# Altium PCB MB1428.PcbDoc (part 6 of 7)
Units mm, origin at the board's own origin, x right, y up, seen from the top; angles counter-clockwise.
Board outline 55.88 x 152.4 mm, 4 copper layers (Top Layer, Signal Layer 1, Signal Layer 2, Bottom Layer), stack 1.614 mm thick; 396 components, 227 nets, 1346 pads, 1469 vias.
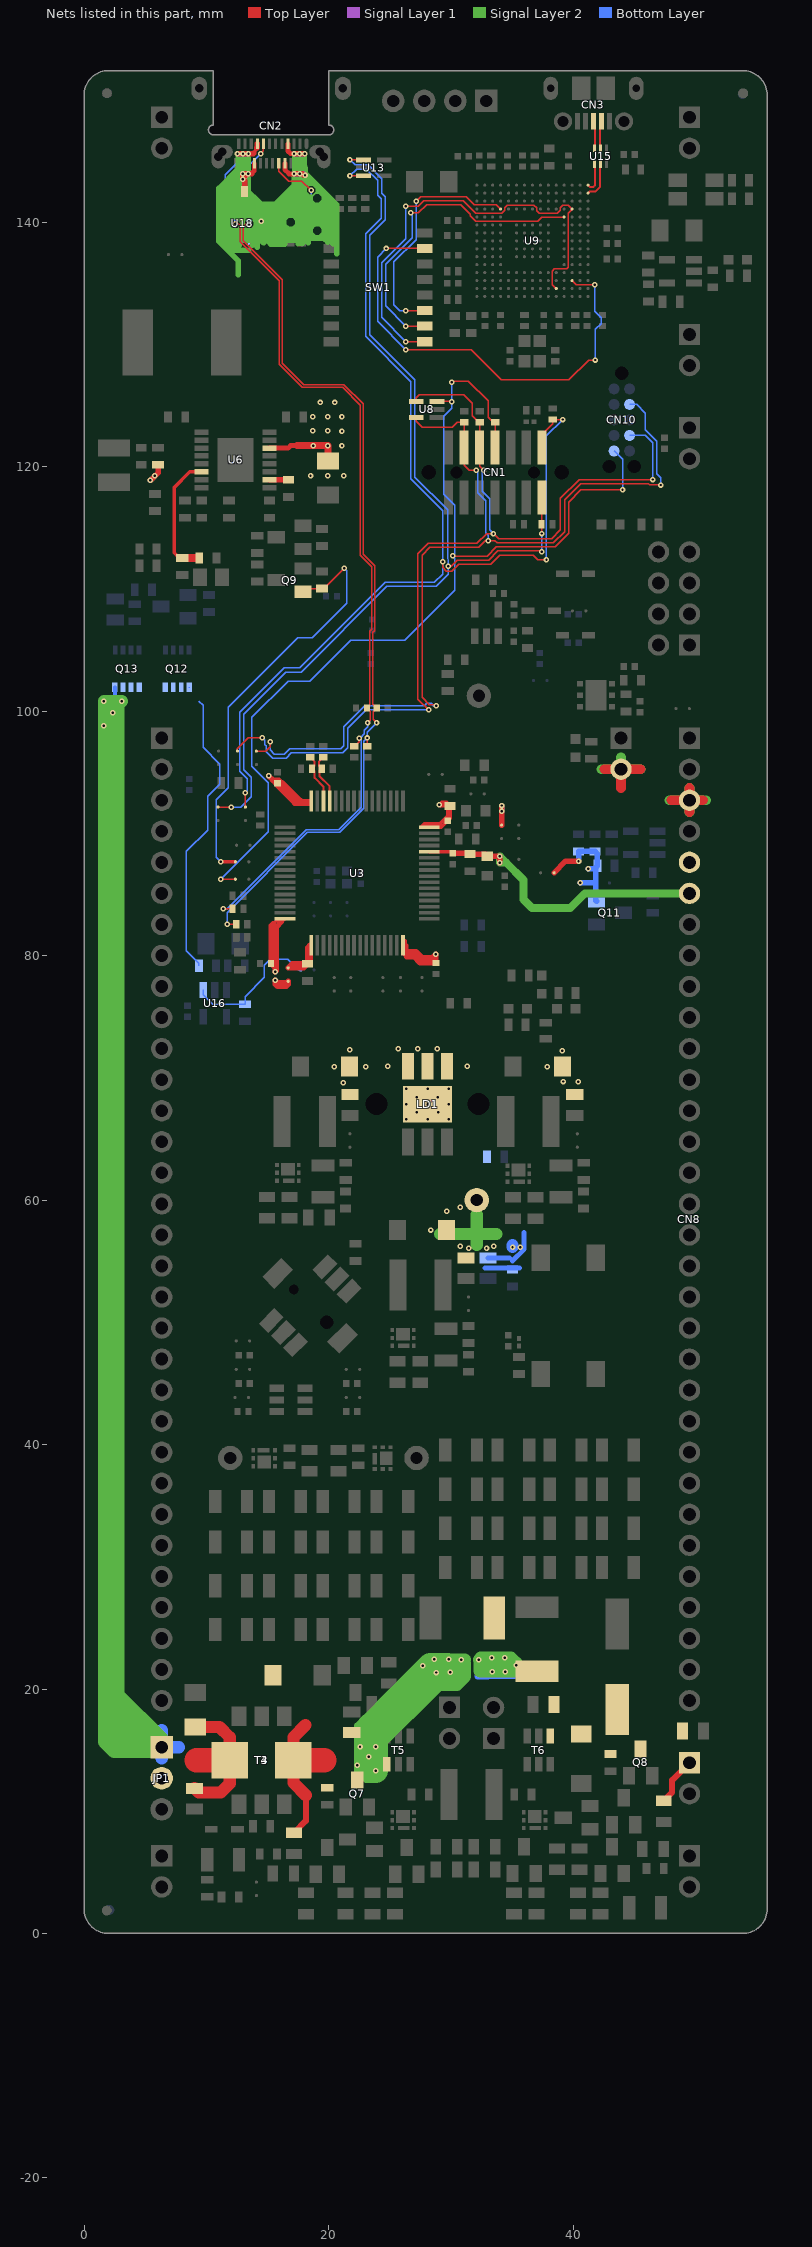
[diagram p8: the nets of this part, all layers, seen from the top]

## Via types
v1: diameter 0.45, hole 0.2, Top Layer to Bottom Layer, tented both sides, 1460 vias
v2: diameter 0.6, hole 0.2, Top Layer to Bottom Layer, tented both sides, 9 vias

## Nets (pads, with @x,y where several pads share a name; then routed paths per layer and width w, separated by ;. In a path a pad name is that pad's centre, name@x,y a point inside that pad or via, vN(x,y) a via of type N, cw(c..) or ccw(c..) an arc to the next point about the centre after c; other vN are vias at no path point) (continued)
T_SWCLK: CN1.6 CN10.4 R112.2 SB27.1 U8.4 | length 78.7
  Top Layer w0.12: SB27.1@12.55,96.725 12.55,96.925 13.45,97.825 v1(14.579,97.825) ; U8.4@27.175,125.332 27.175,125.657 27.418,125.9 31.053,125.9 31.753,125.2 31.753,124.164 32.285,123.632 R112.2@32.375,123.632 32.365,123.622 CN1.6@32.365,121.557 32.365,120.035 v1(32.7,119.7) ; v1(28.182,100.118) 27.318,100.982 27.318,112.888 28.162,113.732 32.137,113.732 32.926,114.52 v1(33.495,114.52) 33.5,114.525 33.925,114.1 38.255,114.1 38.975,114.82 38.975,117.425 40.5,118.95 v1(46.525,118.95)
  Bottom Layer w0.12: v1@14.575,97.825 14.577,97.823 14.793,97.607 14.793,97.252 14.893,97.152 14.893,96.687 15.43,96.15 16.525,96.15 16.968,96.593 21.143,96.593 21.575,97.025 21.575,98.6 23.093,100.118 v1(28.182,100.118) ; v1@32.725,119.725 v1(32.7,119.7) 32.557,119.557 32.557,117.993 33.182,117.368 33.182,114.833 v1(33.495,114.52) ; CN10.4@44.63,122.555 45.918,122.555 46.523,121.95 46.523,118.952 v1(46.525,118.95)
T_SWCLKa: SW1.15 U9.M11 | length 26.1
  Top Layer w0.12: v1(26.325,131.5) SW1.15@27.86,131.5 SW1.15@27.925,131.5 ; v1(26.73,140.775) 27.355,140.775 28.016,141.436 30.818,141.436 31.585,140.669 31.585,140.539 32.044,140.08 37.11,140.08 37.455,140.425 U9.M11@39.28,140.425
  Bottom Layer w0.12: v1(26.325,131.5) 24.678,133.147 24.678,136.547 26.839,138.708 26.839,140.641 26.705,140.775 v1(26.73,140.775)
T_SWDIO: CN1.4 CN10.2 R111.2 SB29.1 U8.5 | length 79
  Top Layer w0.12: SB29.1@14.1,96.725 14.875,96.725 15.225,97.075 v1(15.225,97.5) ; U8.5@27.175,124.032 27.175,123.707 27.657,123.225 30.125,123.225 30.532,123.632 R111.2@31.1,123.632 31.1,121.562 CN1.4@31.095,121.557 31.095,120.13 31.525,119.7 v1(32.075,119.7) ; v1(28.825,100.45) 28.75,100.525 28.245,100.525 27.65,101.12 27.65,112.75 28.3,113.4 32.275,113.4 32.831,113.956 v1(33.077,113.956) 33.6,113.956 33.787,113.768 38.393,113.768 39.307,114.682 39.307,117.287 40.638,118.618 46.162,118.618 46.275,118.505 v1@47.175,118.505
  Bottom Layer w0.12: v1(15.225,97.5) 15.225,96.825 15.568,96.482 16.387,96.482 16.83,96.925 21.005,96.925 21.243,97.163 21.243,98.738 22.955,100.45 27.875,100.45 28.05,100.625 28.382,100.625 28.557,100.45 v1(28.825,100.45) ; v1(32.075,119.7) 32.225,119.55 32.225,117.855 32.85,117.23 32.85,114.6 33.077,114.373 v1(33.077,113.956) ; CN10.2@44.63,125.095 45.21,125.095 45.927,124.378 45.927,123.016 46.855,122.088 46.855,119.42 47.175,119.1 v1(47.175,118.5)
T_SWDIOa: SW1.16 U9.L2 U9.N12 | length 37.5
  Top Layer w0.12: v1(26.325,130.23) SW1.16@27.675,130.23 ; v1(26.325,141.32) 27.348,141.32 27.796,141.768 31.006,141.768 32.024,140.75 34.186,140.75 34.425,140.989 34.425,141.201 34.604,141.38 36.806,141.38 37.025,141.161 37.025,140.919 37.219,140.725 38.711,140.725 38.975,140.989 38.975,141.201 39.154,141.38 39.625,141.38 U9.N12@39.93,141.075 39.605,140.75 39.605,136.3 39.485,136.18 38.485,136.18 38.305,136 38.305,134.9 U9.L2@38.63,134.575
  Bottom Layer w0.12: v1(26.325,130.23) 24.346,132.209 24.346,136.685 26.325,138.664 v1(26.325,141.32)
T_SWO: CN1.8 CN10.6 R113.2 SB16.2 U8.3 | length 85.2
  Top Layer w0.12: v1(11.2,86.25) SB16.2@12.375,86.25 ; U8.3@28.875,125.332 30.073,125.332 v1(30.08,125.325) ; v1(30.15,112.7) 30.164,112.686 32.975,112.686 33.725,113.436 38.53,113.436 39.639,114.545 39.639,117.089 40.65,118.1 v1(44.05,118.1) ; 30.3,126.995 31.43,126.995 33.05,125.375 33.05,124.039 33.457,123.632 R113.2@33.65,123.632 33.635,123.617 CN1.8@33.635,121.557
  Bottom Layer w0.12: v1(11.2,86.25) 15.075,90.125 15.075,94.125 13.725,95.475 13.725,99.489 16.686,102.45 18.461,102.45 21.811,105.8 26.236,105.8 30.34,109.904 30.34,112.51 v1(30.15,112.7) 30.34,112.89 30.34,116.846 29.44,117.746 29.44,124.135 30.08,124.775 v1(30.08,125.325) v1(30.08,126.899) ; CN10.6@43.36,121.285 44.055,120.59 44.055,118.105 v1(44.05,118.1)
T_SWOa: SW1.14 U9.D12 | length 19.4
  Top Layer w0.12: v1(26.325,132.77) SW1.14@27.83,132.77 ; v1(27.18,141.725) 27.555,142.1 31.258,142.1 31.938,141.42 33.735,141.42 U9.D12@34.08,141.075
  Bottom Layer w0.12: v1(26.325,132.77) 25.83,132.77 25.35,133.25 25.35,136.75 27.171,138.571 27.171,141.716 v1(27.18,141.725)
T_VCC_AIN: SW1.10 U9.N3 | length 38.5
  Top Layer w0.12: v1(24.73,137.85) SW1.10@27.86,137.85 SW1.10@27.925,137.85 ; v1(26.329,129.575) 26.354,129.55 31.686,129.55 34.136,127.1 39.66,127.1 41.285,128.725 v1(41.83,128.725) ; U9.N3@39.93,135.225 40.255,134.9 v1(41.78,134.9)
  Bottom Layer w0.12: v1(24.73,137.85) 24.014,137.134 24.014,131.89 v1(26.329,129.575) ; v1(41.78,134.9) 41.78,132.725 42.305,132.2 42.305,131.7 41.83,131.225 v1(41.83,128.725)
T_VCP_RX: CN1.13 R105.2 SB23.1 U13.1 | length 84.3
  Top Layer w0.12: SB23.1@10.95,92.15 v1@12.125,92.15 ; v1(21.755,145.1) U13.1@22.855,145.1 ; v1(29.801,111.855) 30.026,111.855 30.525,112.354 33.113,112.354 33.863,113.104 37.366,113.104 37.425,113.045 v1(37.425,113.031) ; v1(37.425,114.532) R105.2@37.425,115.282 37.445,115.302 CN1.13@37.445,117.493
  Bottom Layer w0.12: v1(12.05,92.15) 12.825,92.15 13.675,93 13.675,94.6 13.05,95.225 13.05,99.755 16.495,103.2 17.775,103.2 24.775,110.2 28.796,110.2 29.801,111.205 v1(29.801,111.855) 29.801,112.384 29.735,112.45 29.735,116.47 27.055,119.15 27.055,127.1 23.362,130.793 23.362,138.912 24.644,140.195 24.644,142.075 24.367,142.353 24.367,143.558 23.243,144.682 22.173,144.682 v1(21.755,145.1) ; v1@37.425,113.045 v1(37.425,114.532)
T_VCP_TX: CN1.14 R114.2 SB24.1 U13.3 | length 94.1
  Top Layer w0.12: SB24.1@13.2,92.15 v1(13.2,93.325) ; v1(21.755,143.8) U13.3@22.855,143.8 ; v1(29.33,112.23) 29.33,111.754 29.634,111.45 30.091,111.45 30.663,112.022 33.25,112.022 34,112.772 36.733,112.772 37.105,112.4 v1(37.83,112.4) ; CN1.14@37.445,121.557 37.445,122.602 38.35,123.507 38.35,123.855 39.173,123.855 v1(39.175,123.857)
  Bottom Layer w0.12: v1(13.2,93.325) 13.343,93.468 13.343,94.462 12.718,95.087 12.718,99.893 16.357,103.532 17.637,103.532 24.637,110.532 28.659,110.532 29.33,111.203 v1(29.33,112.23) 29.33,116.405 26.723,119.012 26.723,126.962 23.03,130.655 23.03,139.05 24.312,140.332 24.312,141.938 24.035,142.215 24.035,143.42 23.105,144.35 22.305,144.35 v1(21.755,143.8) ; v1(37.83,112.4) 37.83,122.512 v1(39.175,123.857)
USB_DEV_HS_CN_N: CN3.2 U15.5 | length 2.3
  Top Layer w0.16: U15.5@42.25,146.05 42.193,146.107 42.193,147.743 42.325,147.875 CN3.2@42.325,148.25
USB_DEV_HS_CN_P: CN3.3 U15.6 | length 2.3
  Top Layer w0.16: CN3.3@41.675,148.25 41.675,147.8 41.807,147.668 41.807,146.107 U15.6@41.75,146.05
USB_DEV_HS_N: U9.R14 U15.2 | length 3.1
  Top Layer w0.16: U9.R14@41.23,142.375 41.355,142.5 41.83,142.5 42.193,142.863 42.193,144.693 U15.2@42.25,144.75
USB_DEV_HS_P: U9.R15 U15.1 | length 2.4
  Top Layer w0.16: U9.R15@41.23,143.025 41.369,142.886 41.67,142.886 41.807,143.023 41.807,144.693 U15.1@41.75,144.75
USB_PD_VBUS: JP1.1 Q13.5 Q13.6 Q13.7 Q13.8 | length 286.5
  Signal Layer 2 w1: 2.805,18.27 2.805,16.945 3.95,15.8 ; 2.805,18.27 5.275,15.8 ; 2.805,18.27 2.805,19.57 ; 2.805,19.57 2.805,100.53 ; 2.805,19.57 6.35,16.025 JP1.1@6.35,15.24 ; 2.805,100.53 v1(3.075,100.8) 1.65,100.8 v1(1.625,100.825) v1(1.625,98.8) 1.625,15.675 2.45,14.85 5.96,14.85 JP1.1@6.35,15.24 ; 2.805,100.53 2.55,100.275 2.55,16.075 2.825,15.8 3.95,15.8 ; 3.95,15.8 4.51,15.24 JP1.1@5.835,15.24 ; 3.95,15.8 5.275,15.8 ; 5.275,15.8 5.79,15.8 JP1.1@6.35,15.24 ; 5.275,15.8 JP1.1@5.835,15.24 ; JP1.1@5.835,15.24 JP1.1@6.35,15.24
  Bottom Layer w0.3: v1(1.625,100.825) 1.65,100.825 1.975,100.5 2.525,101.05 Q13.8@2.525,101.95
  Bottom Layer w1: 4.56,15.24 JP1.1@6.35,15.24 ; JP1.1@6.35,14.325 JP1.1@6.35,15.24 ; 6.35,16.625 JP1.1@6.35,15.24 ; 7.76,15.24 JP1.1@6.35,15.24
  other v1: 2.35,99.85
USBPD_550mA_PROTECT: Q9.1 R98.2 SB19.2 | length 34.7
  Top Layer w0.12: Q9.1@17.925,109.775 18.175,110.025 R98.2@19.475,110.025 19.6,110.025 v1(21.275,111.7)
  Top Layer w0.3: v1(11.2,87.675) SB19.2@12.375,87.675
  Bottom Layer w0.12: v1(11.2,87.675) 10.81,88.065 10.81,92.749 11.81,93.749 11.81,100.335 17.49,106.015 18.651,106.015 21.475,108.839 21.475,111.5 v1(21.275,111.7) 21.27,111.7 v1@21.235,111.665
USBPD_CC1: C38.2 CN2.A5 R85.2 R94.1 U18.1 | length 84.5
  Top Layer w0.12: v1(11.7,82.55) R85.2@12.45,82.55 ; 13.275,139.875 13.015,139.615 13.015,138.497 16.22,135.292 16.22,128.467 17.967,126.72 21.242,126.72 22.82,125.142 22.82,112.844 23.77,111.894 23.77,106.595 23.625,106.45 23.625,100.575 C38.2@23.95,100.25 23.64,99.94 23.64,99.335 v1(23.925,99.05) ; CN2.A5@15.925,144.82 15.925,144.175 16.738,143.362 17.813,143.362 v1(18.575,142.6) ; R94.1@23.164,97.129 v1(23.164,97.804)
  Bottom Layer w0.12: v1(11.7,82.55) 11.7,83.5 18.275,90.075 20.925,90.075 22.9,92.05 22.9,97.54 v1(23.164,97.804) 23.164,98.289 v1(23.925,99.05) ; U18.1@13.875,138.825 13.5,139.2 v1(13.5,139.875) 13.5,140.1 14.325,140.925 18.05,140.925 18.575,141.45 v1(18.575,142.6)
USBPD_CC2: C37.2 CN2.B5 R86.2 R93.1 U18.2 | length 81.3
  Top Layer w0.12: v1(11.4,83.85) R86.2@12.15,83.85 ; 12.6,139.875 12.775,139.7 12.775,138.398 15.98,135.193 15.98,134.9 15.98,128.368 17.868,126.48 21.143,126.48 22.58,125.043 22.58,112.745 23.53,111.795 23.53,106.694 23.385,106.549 23.385,100.485 C37.2@23.15,100.25 23.4,100 23.4,99.265 v1(23.189,99.054) ; v1(14.45,145.6) 14.675,145.825 CN2.B5@14.675,146.42 ; R93.1@22.1,97.125 22.15,97.125 22.525,97.5 v1(22.525,97.8)
  Bottom Layer w0.12: v1(11.4,83.85) 11.711,83.85 18.176,90.315 20.826,90.315 22.66,92.149 22.66,97.665 v1(22.525,97.8) 22.587,97.8 22.924,98.137 22.924,98.449 23.189,98.714 v1(23.189,99.054) ; U18.2@11.975,138.825 12.375,139.225 v1(12.375,139.875) 12.375,140.1 11.55,140.925 11.55,143.878 12.498,144.825 13.675,144.825 v1(14.45,145.6)
USBPD_VBUS: C52.2 C53.2 C105.2 CN2.A4 CN2.A9 CN2.B4 CN2.B9 Q12.5 Q12.6 Q12.7 Q12.8 R110.2 R136.2 U6.10 U6.14 U12.1 | length 250.7
  Top Layer w0.15: 13.83,145.6 13.83,145.749 14.12,146.039 14.175,146.094 CN2.B4@14.175,146.131
  Top Layer w0.25: 13.98,145.75 13.98,145.795 14.175,145.99 CN2.B4@14.175,146.025
  Top Layer w0.3: 14.07,145.92 14.175,146.025 CN2.B4@14.175,146.094
  Top Layer w0.35: 14.095,145.98 14.12,146.005 14.12,146.039 CN2.B4@14.12,146.041
  Top Layer w0.4: 13.7,143.975 13.925,144.2 CN2.A9@13.925,144.82 ; CN2.B4@14.12,146.041 14.145,146.066 CN2.B4@14.145,146.101 ; U6.14@15.175,121.525 16.7,121.525 16.9,121.725 17.45,121.725 ; CN2.A4@16.425,144.82 16.425,144.3 16.775,143.95 v1(17.175,143.95) ; CN2.B9@16.675,146.42 16.675,145.825 16.9,145.6 v1(17.175,145.6) ; v1@17.625,143.95 17.65,143.975 v1@17.67,143.955
  Top Layer w0.45: v1(5.425,118.875) v1(5.8,119.25) 6.05,119.5 R110.2@6.05,120.15 ; v1@12.605,145.6 v1(13,145.6) v1(13.45,145.6) 13.83,145.6 13.88,145.65 ; U12.1@13.125,142.5 13.125,143.375 v1(12.975,143.525) ; 13.7,143.975 v1(13.425,143.975) ; CN2.B4@14.145,146.101 14.175,146.131 CN2.B4@14.175,146.42 ; U6.10@15.175,118.925 C53.2@16.725,118.925 ; v1(17.175,143.95) 17.625,143.95 v1(17.65,143.95) 17.85,143.95 17.975,143.825 v1(18.075,143.825) ; v1(17.175,145.6) v1(17.625,145.6) v1@17.995,145.6 ; v1(12.975,143.525) v1(13.425,143.975) ; v1(12.975,143.525) v1(12.975,143.975) v1(13.425,143.975)
  Top Layer w0.6: 17.45,121.725 v1(19.925,121.725) 19.95,121.7 C52.2@19.95,120.475
  Signal Layer 1 w0.45: v1@12.605,145.6 v1(13,145.6) v1(13.45,145.6) ; v1(17.175,143.95) v1(17.65,143.95) 17.95,143.95 v1(18.075,143.825) ; v1(17.175,145.6) v1(17.625,145.6) v1@17.995,145.6 ; v1(12.975,143.525) v1(13.425,143.975) v1(12.975,143.975) v1(12.975,143.525)
  Signal Layer 2 w0.12: 18.005,142.214 18.101,142.118 18.67,142.118 ; 18.005,142.975 18.074,142.906 18.17,142.81 18.17,142.432 18.407,142.195 18.743,142.195 18.98,142.432 18.98,142.768 18.743,143.005 18.504,143.005 18.339,143.17 ; 18.559,141.659 18.67,141.77 18.67,142.118 ; 18.975,141.545 19.243,141.545 19.48,141.782 19.48,142.118 19.243,142.355 18.907,142.355 18.67,142.118
  Signal Layer 2 w0.4: 11.83,139.85 11.83,139.649 12.149,139.33 12.601,139.33 12.955,139.684 ; 13,139.3 12.955,139.345 12.955,139.649 ; 13.511,140.445 13.486,140.42 13.274,140.42 12.955,140.101 12.955,139.684 ; 14.281,139.2 14.175,139.2 13.404,139.2 13.304,139.3 12.955,139.649 ; 12.955,139.649 12.955,139.684
  Signal Layer 2 w0.45: v1(5.425,118.875) v1(5.8,119.25) v1@5.8,119.275 ; 12,140.375 12.213,140.588 ; 12.35,139.3 13,139.3 13.304,139.3 ; 12.425,138 11.7,138.725 11.7,139.25 ; 12.6,135.7 12.6,136.85 11.025,138.425 11.025,142.765 12.605,144.345 ; 12.7,138.125 12,138.825 12,138.95 ; 12.938,140.119 12.611,140.445 ; 13.475,137.725 12.3,137.725 ; 13.595,139.3 13.304,139.3 ; 13.775,138.1 13.845,138.17 13.845,138.525 ; 14.002,139.057 13.845,138.9 ; 14.175,137.95 14.175,138.825 ; 14.281,139.2 15.281,138.2 16.4,138.2 ; 14.7,138.3 14.175,138.825 ; 17.525,138.25 17.525,138.513 ; 17.825,138.225 17.95,138.35 17.95,138.675 ; 18.03,144.767 18.03,144.51 ; 18.101,142.118 18.189,142.03 ; 18.35,138.3 18.35,138.675 ; 18.505,139.25 18.505,139.536 18.569,139.6 ; 18.505,142.03 18.189,142.03 ; 19.145,142.52 19.145,142.836 ; 20.35,138.225 20.35,140.053 19.703,140.7 18.7,140.7 17.65,141.75 17.65,142.4 ; 20.675,137.4 20.675,140.225 ; 11.4,138.625 12.3,137.725 ; 11.4,138.625 11.4,138.375 12.05,137.725 12.3,137.725 ; 11.4,138.625 11.4,142.67 11.69,142.96 ; 11.69,142.96 11.69,140.66 11.7,140.65 ; 11.69,142.96 11.915,143.185 ; 11.7,139.25 12,138.95 ; 11.7,139.25 11.7,139.649 ; 11.7,139.649 11.805,139.754 11.805,140.111 ; 11.7,139.649 11.7,140.006 ; 11.7,140.006 11.7,140.65 ; 11.7,140.006 11.805,140.111 ; 11.7,140.65 11.937,140.888 ; 11.805,140.111 12.139,140.445 12.355,140.445 ; 11.915,143.185 11.915,140.91 11.937,140.888 ; 11.915,143.185 12.277,143.548 ; 11.937,140.888 12.277,141.227 12.277,143.548 ; 12,138.95 12.05,138.9 ; 12.05,138.9 13.845,138.9 ; 12.05,138.9 12.425,138.525 13.845,138.525 ; 12.213,140.588 12.462,140.588 ; 12.213,140.588 12.605,140.98 12.605,141.25 ; 12.213,140.588 12.338,140.463 ; 12.277,143.548 12.605,143.875 ; 12.338,140.463 12.355,140.445 ; 12.338,140.463 12.462,140.588 ; 12.355,140.445 12.611,140.445 ; 12.462,140.588 12.916,141.041 ; 12.462,140.588 12.775,140.588 ; 12.605,141.25 12.706,141.25 12.916,141.041 ; 12.605,141.25 12.605,141.8 ; 12.605,141.8 12.605,143.875 ; 12.605,141.8 12.927,141.477 ; 12.605,143.875 12.605,144.345 ; 12.605,144.345 12.605,145.6 v1(13,145.6) ; 12.605,144.345 v1(12.975,143.975) ; 12.611,140.445 12.918,140.445 ; 12.775,140.588 12.918,140.445 ; 12.775,140.588 13.369,140.588 ; 12.916,141.041 12.927,141.052 12.927,141.477 ; 12.916,141.041 13.369,140.588 ; 12.918,140.445 13.511,140.445 ; 12.927,141.477 13.845,140.56 ; 12.975,142.478 13.845,141.608 ; 12.975,142.478 12.975,141.895 13.845,141.025 ; 12.975,142.478 v1(12.975,143.525) ; v1(12.975,143.525) v1(13.425,143.975) ; v1(12.975,143.525) v1(12.975,143.975) ; v1(12.975,143.975) v1(13.425,143.975) ; v1(12.975,143.975) 13,144 v1(13,145.6) ; v1(13,145.6) v1(13.45,145.6) 13.45,144 v1(13.425,143.975) ; 13.304,139.3 13.309,139.305 13.736,139.305 14.07,139.639 14.07,140.111 13.736,140.445 13.511,140.445 ; 13.369,140.588 13.511,140.445 ; v1(13.425,143.975) 13.425,142.525 14.175,141.775 ; 13.845,138.525 13.845,138.9 ; 13.845,138.9 14.1,138.9 14.175,138.825 ; 13.845,140.56 13.845,141.025 ; 13.845,140.56 13.845,140.35 14.131,140.35 14.175,140.306 ; 13.845,141.025 13.845,141.105 ; 13.845,141.105 13.845,141.608 ; 13.845,141.105 14.175,140.775 ; 13.845,141.608 14.175,141.278 ; 14.175,138.825 14.175,139.2 14.175,139.781 ; 14.175,139.781 14.175,140.306 ; 14.175,139.781 15.506,138.45 15.906,138.45 15.969,138.513 ; 14.175,140.306 15.969,138.513 ; 14.175,140.306 14.175,140.775 ; 14.175,140.775 16.175,138.775 17.525,138.775 ; 14.175,140.775 14.175,141.278 ; 14.175,141.278 14.689,140.764 ; 14.175,141.278 14.175,141.775 ; 14.175,141.775 14.5,141.45 ; 14.5,141.45 14.825,141.125 ; 14.5,141.45 15.625,141.45 17.175,143 ; 14.689,140.764 14.964,140.489 ; 14.689,140.764 15.186,140.764 ; 14.825,141.125 15.186,140.764 ; 14.825,141.125 15.9,141.125 17.175,142.4 ; 14.964,140.489 16.378,139.075 17.475,139.075 17.525,139.125 ; 14.964,140.489 15.045,140.57 15.38,140.57 ; 15.186,140.764 16.089,140.764 ; 15.186,140.764 15.38,140.57 ; 15.38,140.57 15.95,140 ; 15.38,140.57 16.295,140.57 ; 15.95,140 16.52,139.43 16.664,139.43 ; 15.95,140 15.95,140.225 16.295,140.57 ; 15.969,138.513 17.525,138.513 ; 16.089,140.764 16.489,140.764 ; 16.089,140.764 17.175,141.85 ; 16.295,140.57 16.489,140.764 ; 16.295,140.57 16.664,140.57 ; 16.489,140.764 17.125,141.4 17.175,141.4 ; 16.489,140.764 17.175,140.764 ; 16.664,139.43 17.136,139.43 ; 16.664,139.43 16.33,139.764 16.33,140.236 16.664,140.57 ; 16.664,140.57 17.136,140.57 17.175,140.531 ; 17.136,139.43 17.454,139.747 ; 17.136,139.43 17.208,139.43 17.525,139.747 ; 17.175,140.531 17.175,140.764 ; 17.175,140.531 17.47,140.236 ; 17.175,140.764 17.175,141.4 ; 17.175,140.764 17.189,140.764 17.425,141 ; 17.175,141.4 17.175,141.85 ; 17.175,141.85 17.175,142.4 ; 17.175,141.85 17.425,142.1 ; 17.175,142.4 17.175,143 ; 17.175,142.4 17.425,142.65 ; 17.175,143 v1(17.175,143.95) ; 17.175,143 17.425,143.25 ; v1(17.175,143.95) 17.22,143.995 17.22,145.555 v1(17.175,145.6) v1(17.625,145.6) ; v1(17.175,143.95) 17.425,143.95 ; 17.425,141 17.425,140.697 17.95,140.172 ; 17.425,141 17.425,141.425 ; 17.425,141 17.975,140.45 ; 17.425,141.425 17.425,142.1 ; 17.425,141.425 18.502,140.348 19.477,140.348 19.9,139.925 ; 17.425,142.1 17.425,142.65 ; 17.425,142.65 17.425,143.25 ; 17.425,143.25 17.425,143.95 ; 17.425,143.95 v1(17.65,143.95) ; 17.454,139.747 17.47,139.764 17.47,140.236 ; 17.454,139.747 17.525,139.747 ; 17.47,140.236 17.525,140.181 17.525,139.747 ; 17.525,138.513 17.525,138.775 ; 17.525,138.775 17.525,139.125 ; 17.525,139.125 17.525,139.747 ; 17.525,139.747 17.95,140.172 ; v1(17.625,145.6) 17.625,143.975 v1(17.65,143.95) ; v1(17.625,145.6) 17.995,145.6 17.995,144.475 ; 17.65,142.4 v1(17.65,143.95) ; 17.65,142.4 18.005,142.045 ; v1(17.65,143.95) 17.95,143.95 v1@17.995,143.905 ; 17.95,138.675 18.35,138.675 ; 17.95,138.675 17.95,140.172 ; 17.975,140.45 18.1,140.45 18.625,139.925 18.675,139.925 ; 17.975,140.45 18.35,140.075 18.35,139.6 ; v1@17.995,143.905 17.995,144.475 ; v1@17.995,143.905 v1@18.03,143.87 ; 17.995,144.475 18.03,144.44 ; 17.995,144.475 18.03,144.51 ; 18.005,142.045 18.005,142.214 18.005,142.836 ; 18.005,142.045 18.005,141.92 18.8,141.125 19.775,141.125 ; 18.005,142.045 18.02,142.03 18.189,142.03 ; 18.005,142.836 18.074,142.906 18.339,143.17 18.385,143.17 ; 18.005,142.836 18.005,142.975 ; 18.005,142.975 18.005,143.55 ; 18.005,142.975 18.075,143.045 18.075,143.48 ; 18.005,143.55 18.005,143.755 v1@18.05,143.8 ; 18.005,143.55 18.075,143.48 ; v1@18.03,143.87 18.03,144.44 ; v1@18.03,143.87 v1@18.05,143.85 ; 18.03,144.44 18.05,144.42 ; 18.03,144.44 18.03,144.51 ; 18.03,144.51 18.05,144.53 18.05,144.42 ; v1@18.05,143.8 v1@18.05,143.85 ; v1@18.05,143.8 v1(18.075,143.825) ; v1@18.05,143.85 18.05,144.42 ; v1@18.05,143.85 v1(18.075,143.825) ; 18.05,144.42 18.075,144.395 v1@18.075,144.019 ; 18.075,143.48 v1(18.075,143.825) ; 18.075,143.48 18.385,143.17 ; v1(18.075,143.825) v1@18.075,144.019 ; v1@18.075,144.019 20.675,141.419 ; 18.189,142.03 18.559,141.659 18.839,141.38 19.311,141.38 ; 18.35,138.675 18.35,139.219 ; 18.35,138.675 18.9,138.675 ; 18.35,139.219 18.35,139.6 ; 18.35,139.219 18.839,138.73 18.845,138.73 ; 18.35,139.6 18.675,139.925 ; 18.35,139.6 18.569,139.6 ; 18.385,143.17 18.811,143.17 19.145,142.836 ; 18.569,139.6 18.839,139.87 ; 18.675,139.925 18.894,139.925 ; 18.839,139.87 19.311,139.87 19.425,139.756 ; 18.839,139.87 18.894,139.925 ; 18.845,138.73 18.9,138.675 ; 18.845,138.73 19.311,138.73 19.645,139.064 ; 18.894,139.925 19.425,139.925 ; 18.9,138.675 19.375,138.675 ; 19.145,142.836 19.645,142.336 ; 19.311,141.38 20.05,141.38 ; 19.311,141.38 19.645,141.714 19.645,142.336 ; 19.375,138.675 19.645,138.945 19.645,139.064 ; 19.375,138.675 19.65,138.675 19.95,138.375 19.95,139.875 19.9,139.925 ; 19.425,139.756 19.425,139.925 ; 19.425,139.756 19.645,139.536 19.645,139.064 ; 19.425,139.925 19.9,139.925 ; 19.645,142.336 20.05,141.931 20.05,141.38 ; 19.775,141.125 20.05,141.125 ; 19.775,141.125 20.381,140.519 ; 20.05,141.125 20.381,141.125 ; 20.05,141.125 20.05,141.38 ; 20.05,141.38 20.636,141.38 ; 20.381,140.519 20.675,140.225 ; 20.381,140.519 20.381,141.125 ; 20.381,141.125 20.636,141.38 ; 20.636,141.38 20.675,141.419 ; 20.675,140.225 20.675,141.419
  Bottom Layer w0.12: Q12.5@8.6,101.925 Q12.5@8.625,101.95 ; 9.375,100.825 9.738,100.462 9.738,97.037 11.1,95.675 11.1,94.025 10.1,93.025 10.1,90.275 8.35,88.525 8.35,80.405 9.4,79.355 R136.2@9.4,79.175
  Bottom Layer w0.45: v1@12.605,145.6 v1(13,145.6) v1(13.45,145.6) ; v1(14.5,140.075) 15.225,140.075 C105.2@15.4,139.9 ; v1(17.175,143.95) v1(17.65,143.95) 17.95,143.95 v1(18.075,143.825) ; v1(17.175,145.6) v1(17.625,145.6) v1@17.995,145.6 ; v1(12.975,143.525) v1(13.425,143.975) v1(12.975,143.975) v1(12.975,143.525)
  other v1: 18.525,119.275 19.95,119.275 21.25,119.275 18.75,121.7 21.1,121.725 21.1,122.9 18.725,122.925 19.925,122.925 21.1,124.075 18.725,124.1 19.925,124.1 19.325,125.25 20.525,125.25 12.55,145.6 18.05,145.6
USBPD_VIN: R134.2 SB33.1 U16.1 | length 11.5
  Bottom Layer w0.12: U16.1@9.75,77.2 9.75,76.8 10.525,76.025 R134.2@13.175,76.025 13.175,76.65 14.75,78.225 14.75,79.2 15.25,79.7 16.65,79.7 17.525,78.825 SB33.1@17.725,78.825
USBPDFS_D_N: R91.2 R96.2 U3.45 | length 4.2
  Top Layer w0.16: R96.2@19.564,96.229 19.232,95.897 19.232,95.511 R91.2@19.439,95.304 19.25,95.115 19.25,94.693 20.089,93.854 U3.45@20.089,92.654
USBPDFS_D_P: R90.2 R95.2 U3.46 | length 4.2
  Top Layer w0.16: R95.2@18.514,96.229 18.846,95.897 18.846,95.511 R90.2@18.639,95.304 18.864,95.079 18.864,94.533 19.589,93.808 U3.46@19.589,92.654
V_IN: C6.2 D5.2 Q7.3 R17.2 R23.2 R132.1 T3.7 T4.7 T5.4 | length 94
  Top Layer w0.5: R17.2@17.175,8.25 18.15,9.225 18.15,11.3
  Top Layer w1: 18.125,17.05 17.125,16.05 T3.7@17.125,14.175 17.125,12.325 18.15,11.3
  Top Layer w2: T3.7@17.125,14.175 19.65,14.175
  Signal Layer 2 w0.5: 23.3,13.9 23.852,13.348 23.852,12.549 23.076,12.549 22.35,13.275 v1(22.35,13.75) 22.35,16.732 ; 23.3,16.912 22.53,16.912 22.35,16.732 ; 25.181,18.794 24.951,19.024 24.374,19.024 22.35,17 22.35,16.732
  Signal Layer 2 w1: v1@28.825,22.425 v1@29.8,22.425 ; 29.2,20.35 30.5,20.35 31.175,21.025 31.175,21.506 ; 29.625,21.95 30.725,21.95 ; v1@29.8,21.475 30.25,21.475 ; v1@29.825,22.45 v1@29.8,22.425 ; v1@29.8,22.425 v1(29.825,22.425) 31.15,22.425 31.125,22.4 v1(30.875,22.4) ; 30.25,21.475 31.144,21.475 ; 30.25,21.475 30.725,21.95 ; 30.725,21.95 30.875,22.1 ; 30.875,22.1 30.875,21.806 31.144,21.537 ; 30.875,22.1 v1(30.875,22.4) ; v1(30.875,22.4) 31.144,22.131 31.144,21.537 ; 31.144,21.475 31.144,21.537 ; 31.144,21.475 31.175,21.506 ; 31.144,21.537 31.175,21.506
  Signal Layer 2 w2: 23.3,13.9 v1(23.3,14.45) 23.3,16.912 23.852,17.464 ; 28.528,20.57 23.875,15.917 v1(23.875,15.275) v1(23.875,13.325) 23.852,13.348 23.852,16.402 ; 29.075,21.625 23.852,16.402 ; 29.35,21.05 29.375,21.05 v1@29.8,21.475 ; 29.625,21.95 28.338,21.95 25.181,18.794 23.852,17.464 ; 23.852,16.402 23.852,17.464
  Bottom Layer w0.5: v1@27.7,21.875 27.7,22.25 27.875,22.425 v1(28.65,22.425) 29.15,22.425 ; v1(30.875,22.4) v1@30.975,22.4 ; R132.1@31.15,21.025 30.325,21.025 ; R132.1@31.175,21.1 31.175,21.275 R132.1@31,21.45 ; R132.1@31.2,21.45 R132.1@31,21.45 ; v1(27.701,21.887) 27.913,21.675 ; v1(27.701,21.887) 27.814,22 29.575,22 ; v1(27.701,21.887) 27.701,21.274 27.95,21.025 30.325,21.025 ; 27.913,21.675 29.675,21.675 v1(29.975,21.375) ; 27.913,21.675 28.238,21.35 v1(28.825,21.35) 29.95,21.35 v1(29.975,21.375) ; 29.15,22.425 29.575,22 ; 29.15,22.425 v1(29.825,22.425) v1@29.85,22.425 ; 29.575,22 29.975,22 ; 29.575,22 v1@29.975,21.6 ; v1@29.85,22.425 30.225,22.425 ; v1@29.85,22.425 30.1,22.175 29.975,22.05 29.975,22 ; v1(29.975,21.375) 30.325,21.025 ; v1(29.975,21.375) v1@29.975,21.4 ; v1(29.975,21.375) v1@30,21.375 ; v1@29.975,21.4 v1@29.975,21.6 ; v1@29.975,21.4 30.075,21.5 v1@29.975,21.6 ; v1@29.975,21.6 29.975,22 ; 29.975,22 30.575,22 30.612,22.038 ; v1@30,21.375 30.637,22.013 ; v1@30,21.375 30.025,21.375 30.1,21.45 R132.1@31,21.45 ; 30.225,22.425 v1@31,22.425 ; 30.225,22.425 30.612,22.038 ; 30.612,22.038 v1@30.975,22.4 ; 30.612,22.038 30.637,22.013 ; 30.637,22.013 v1@31.025,22.4 ; 30.637,22.013 R132.1@31.025,21.625 ; v1@30.975,22.4 v1@31,22.425 ; v1@30.975,22.4 v1@31.025,22.4 ; R132.1@31,21.45 31.025,21.475 R132.1@31.025,21.625 ; v1@31,22.425 v1@31.025,22.4 ; R132.1@31.025,21.625 v1@31.025,22.4 ; R132.1@31.025,21.625 31.18,21.47 31.18,22.395 31.175,22.4 v1@31.025,22.4
  other v1: 22.575,15.275
V_LED: C17.2 C20.2 C21.2 C86.2 C87.2 D6.2 D7.2 D8.2 LD1.4 LD1.5 LD1.6 LD1.7 R133.2 TP3.1 | length 14.5
  Signal Layer 2 w1: 29.125,57.225 32.125,57.225 ; 32.125,56.325 32.125,57.225 ; 32.125,58.8 32.125,57.225 ; 33.75,57.225 32.125,57.225
  Bottom Layer w0.4: 32.8,54.45 35.625,54.45 ; C87.2@33.05,55.275 34.8,55.275 ; 35.05,55.025 36,55.975 36,57.35
  Bottom Layer w1: v1(35.05,56.15) v1@35.05,56.3
  other v1: 31.475,56.05 32.925,56.075 35.7,56.15 30.775,56.225 33.525,56.225 28.35,57.55 29.675,59.1 30.775,59.4 26.375,66.625 28.125,66.625 29.825,66.625 27.2,67.175 28.975,67.175 26.375,67.825 28.1,67.85 29.85,67.85 27.2,68.425 28.95,68.425 26.375,69.1 28.1,69.1 29.825,69.1 21.2,69.6 40.425,69.675 39.2,69.7 20.475,70.925 23.05,70.925 37.875,70.925 24.85,70.95 31.35,70.95 39.125,72.2 21.725,72.3 25.7,72.375 27.3,72.375 28.9,72.375
VBAT: C23.2 SB15.2 U3.1 | length 6.7
  Top Layer w0.25: C23.2@18.289,79.329 18.589,79.629 U3.1@18.589,80.854
  Top Layer w0.45: U3.1@18.502,80.854 18.289,80.641 C23.2@18.289,79.329 ; C23.2@18.289,79.329 17.96,79 SB15.2@16.7,79 17.05,79.35 18.268,79.35 C23.2@18.289,79.329
VC: C48.2 R100.2 U6.6 | length 10.3
  Top Layer w0.3: R100.2@7.8,112.525 7.375,112.95 7.375,118.294 8.656,119.575 U6.6@9.625,119.575
  Top Layer w0.65: R100.2@7.9,112.525 C48.2@9.425,112.525
VDD: C24.2 C25.2 C30.2 C32.2 C33.2 CN8.3 JP4.2 SB15.1 SB21.1 U3.16 U3.32 U3.48 U3.64 | length 63.5
  Top Layer w0.25: U3.16@26.089,80.854 26.089,80.154 26.414,79.829
  Top Layer w0.3: 15.475,82.6 15.879,83.004 U3.64@16.379,83.004 ; 16.15,82.775 U3.64@16.379,83.004 ; U3.64@16.439,83.004 U3.64@16.379,83.004 ; 17.714,92.654 U3.48@18.589,92.654 18.41,92.475 18.375,92.475 ; 26.3,80.825 26.271,80.854 ; U3.32@27.6,90.525 27.85,90.775 28.025,90.775 ; C30.2@29.739,91.031 C30.2@29.733,91.025 ; 26.271,80.854 26.271,81.196 26.089,81.014 U3.16@26.089,80.854 26.271,80.854 ; 28.025,90.775 29.1,90.775 29.35,91.025 ; 28.025,90.775 28.025,90.718 U3.32@28.239,90.504 29.212,90.504 C30.2@29.733,91.025 ; 29.35,91.025 29.75,91.425 ; 29.35,91.025 C30.2@29.733,91.025 ; C30.2@29.733,91.025 C30.2@29.75,91.025 ; C30.2@29.75,91.025 29.75,91.425 ; C30.2@29.75,91.025 29.95,91.225 C32.2@29.95,92.25 ; 29.75,91.425 29.75,92.05 C32.2@29.95,92.25 ; C32.2@29.95,92.25 29.675,92.525 29.275,92.525 v1(29.075,92.325) 29.15,92.25 C32.2@29.95,92.25
  Top Layer w0.45: v1(15.1,94.702) 15.451,94.351 ; 15.475,82.6 15.3,82.425 C25.2@15.3,79.35 ; 16.15,82.775 15.725,82.35 15.725,79.775 ; 17.714,92.654 17.689,92.654 16.243,94.1 16.175,94.1 ; 18.375,92.475 17.25,92.475 15.825,93.9 C33.2@15.825,94.1 ; 26.3,80.825 26.3,80.35 26.325,80.325 27.15,80.325 27.65,79.825 28.4,79.825 ; 26.414,79.908 26.985,79.908 27.489,79.404 C24.2@28.789,79.404 C24.2@28.789,79.436 ; SB21.1@34.164,90.679 v1(34.164,91.804) v1(34.164,92.279) ; C25.2@15.3,79.35 15.625,79.025 v1(15.625,78.675) 15.725,78.775 15.725,79.775 ; C25.2@15.3,79.35 15.725,79.775 ; 15.451,94.351 15.924,94.351 16.175,94.1 ; 15.451,94.351 15.702,94.1 C33.2@15.825,94.1 ; C33.2@15.825,94.1 16.175,94.1 ; 28.4,79.825 C24.2@28.789,79.436 ; 28.4,79.825 28.503,79.825 v1(28.789,80.111) C24.2@28.789,79.436 ; 15.625,77.675 15.825,77.475 16.525,77.475 16.7,77.65 SB15.1@16.7,77.9 16.575,77.775 15.85,77.775 v1(15.625,78) 15.625,77.675
  Top Layer w0.8: 42.575,95.25 JP4.2@43.93,95.25 ; 43.93,93.705 JP4.2@43.93,95.25 ; 45.525,95.25 JP4.2@43.93,95.25 ; 48.035,92.71 CN8.3@49.53,92.71 ; 49.53,91.755 CN8.3@49.53,92.71 ; 49.53,93.705 CN8.3@49.53,92.71 ; 50.66,92.71 CN8.3@49.53,92.71
  Signal Layer 2 w0.45: v1(34.164,91.804) v1(34.164,92.279)
  Signal Layer 2 w0.8: 42.325,95.25 JP4.2@43.93,95.25 ; 43.93,93.77 JP4.2@43.93,95.25 ; 43.93,96.22 JP4.2@43.93,95.25 ; 45.525,95.25 JP4.2@43.93,95.25 ; 47.885,92.71 CN8.3@49.53,92.71 ; 49.53,91.72 CN8.3@49.53,92.71 ; 49.53,93.705 CN8.3@49.53,92.71 ; 50.885,92.71 CN8.3@49.53,92.71
  Bottom Layer w0.45: v1(34.164,91.804) v1(34.164,92.279)
VIN: C4.2 C8.2 JP1.2 T3.8 T4.8 | length 13
  Top Layer w1: C4.2@9.025,11.875 9.375,11.525 11.175,11.525 11.925,12.275 T3.8@11.925,14.175 11.925,16.05 11.075,16.9 C8.2@9.1,16.9
  Top Layer w2: 9.2,14.175 T3.8@11.925,14.175
VOUT: C5.2 C7.1 C9.2 CN7.1 D3.2 F1.2 F2.2 Q8.3 R22.2 R26.2 R132.2 T6.4 | length 46.2
  Top Layer w0.5: R22.2@47.425,10.875 48.1,11.55 48.1,12.54 CN7.1@49.53,13.97
  Signal Layer 2 w1: v1(32.3,22.4) 32.46,22.56 v1(34.425,22.56) 34.933,22.56 35.352,22.14 v1(35.352,21.95) ; v1(32.3,22.4) v1@32.35,22.35 ; v1(32.3,22.4) 33.6,22.4 33.6,21.95 ; v1@32.35,22.35 32.75,21.95 ; v1@32.35,22.35 32.35,21.475 32.4,21.425 v1@33.275,21.425 ; 32.75,21.95 v1@33.275,21.425 ; 32.75,21.95 33.6,21.95 ; v1@33.275,21.425 v1(33.4,21.425) v1(34.45,21.425) 35.275,21.425 35.352,21.502 v1(35.352,21.95) ; v1@33.275,21.425 33.6,21.75 33.6,21.95 ; 33.6,21.95 v1(35.352,21.95)
  Bottom Layer w0.5: R132.2@32.2,21.05 32.202,21.048 R132.2@32.702,21.048 ; R132.2@32.2,21.15 32.2,22.3 v1(32.3,22.4) ; R132.2@32.225,21.15 32.225,21.275 R132.2@32.35,21.4 ; 32.85,21.05 33.025,21.05 ; 33.05,21.725 33.05,21.45 ; v1@35.35,21.975 35.35,22.3 35.025,22.625 32.525,22.625 v1(32.3,22.4) ; R132.2@32.3,21.45 R132.2@32.4,21.45 ; R132.2@32.3,21.45 R132.2@32.35,21.4 ; R132.2@32.3,21.45 v1(32.3,22.4) ; R132.2@32.3,21.45 32.837,21.988 ; v1(32.3,22.4) v1@32.425,22.4 ; R132.2@32.35,21.4 R132.2@32.4,21.45 ; R132.2@32.35,21.4 R132.2@32.702,21.048 ; R132.2@32.4,21.45 32.95,21.45 ; v1@32.425,22.4 32.625,22.2 ; v1@32.425,22.4 32.95,22.4 ; 32.625,22.2 32.837,21.988 ; 32.625,22.2 32.95,22.2 ; R132.2@32.702,21.048 33.023,21.048 33.025,21.05 ; R132.2@32.702,21.048 33.05,21.395 33.05,21.45 ; 32.837,21.988 32.95,22.1 ; 32.837,21.988 32.95,21.875 ; 32.95,21.45 33.05,21.45 ; 32.95,21.45 32.95,21.875 ; 32.95,21.875 32.95,22.1 ; 32.95,21.875 v1@33.375,21.45 ; 32.95,22.1 32.95,22.2 ; 32.95,22.1 33.05,22.2 ; 32.95,22.2 32.95,22.4 ; 32.95,22.2 33.05,22.2 ; 32.95,22.4 v1@33.25,22.4 ; 32.95,22.4 33.1,22.25 ; 33.025,21.05 v1(33.4,21.425) ; 33.025,21.05 35.2,21.05 ; 33.05,21.45 v1@33.375,21.45 ; 33.05,22.2 33.1,22.25 ; 33.05,22.2 33.15,22.2 ; 33.1,22.25 33.15,22.2 ; 33.1,22.25 v1@33.25,22.4 ; 33.15,22.2 33.4,21.95 v1@33.4,21.45 ; 33.15,22.2 33.6,22.2 ; v1@33.25,22.4 33.6,22.4 33.6,22.2 ; v1@33.375,21.45 v1(33.4,21.425) ; v1@33.375,21.45 v1@33.4,21.45 ; v1(33.4,21.425) v1@33.4,21.45 ; v1(33.4,21.425) v1@33.425,21.45 ; v1@33.4,21.45 v1@33.425,21.45 ; v1@33.425,21.45 v1@33.575,21.45 ; v1@33.425,21.45 33.6,21.625 33.6,22.2 ; v1@33.575,21.45 33.875,21.75 35.152,21.75 ; v1@33.575,21.45 34.852,21.45 35.152,21.75 ; 33.6,22.2 35.102,22.2 v1(35.352,21.95) ; 35.152,21.75 v1(35.352,21.95) ; 35.152,21.75 35.2,21.702 35.2,21.05 ; 35.2,21.05 35.352,21.202 v1(35.352,21.95)
  other v1: 33.35,22.575
VREF: C95.2 C96.2 CN8.5 Q11.2 R138.2 SB18.1 SB37.2 | length 10.8
  Top Layer w0.45: SB18.1@38.45,86.775 39.4,87.725 v1(40.45,87.725)
  Bottom Layer w0.45: v1(40.45,87.725) C96.2@40.45,88.525 C95.2@41.8,88.525 42,88.325 R138.2@42,87.35 R138.2@41.875,87.225 ; v1(40.575,85.95) 40.7,85.95 SB37.2@41.875,85.95 ; v1(41.25,87.1) 41.75,87.1 R138.2@41.875,87.225 ; Q11.2@41.925,84.45 41.875,84.5 SB37.2@41.875,85.95 ; SB37.2@41.875,85.95 R138.2@41.875,87.225
VREFP: C27.2 C28.1 CN8.6 L5.2 U3.28 | length 26
  Top Layer w0.3: U3.28@28.239,88.504 30.039,88.504 C28.1@30.164,88.379 C28.1@30.239,88.304
  Top Layer w0.45: C28.1@30.439,88.379 31.489,88.379 C27.2@31.564,88.304 32.814,88.304 L5.2@32.989,88.129 v1(34.014,88.129) v1(34.014,87.604)
  Signal Layer 2 w0.65: CN8.6@49.53,85.09 40.965,85.09 39.775,83.9 36.65,83.9 35.955,84.595 35.955,86.188 34.539,87.604 ; 34.539,87.604 v1(34.014,88.129) v1(34.014,87.604) 34.539,87.604
pads on no net: B2.NPTH1 B2.NPTH2 CART-1.1 CN1.0 CN1.1 CN1.2 CN1.9 CN2.A2 CN2.A3 CN2.A8 CN2.A10 CN2.A11 CN2.B2 CN2.B3 CN2.B8 CN2.B10 CN2.B11 CN3.4 CN10.1 CN10.7 CN10.8 CN10.9 CN10.11 CN10.12 CN10.13 D2.2 D4.2 LPB1.NPTH1 LPB1.NPTH2 MIRE-PL1.1 MIRE-PL2.1 MIRE-PL3.1 MIRE-PL4.1 MIRE-PL5.1 MIRE-PL6.1 T3.2 T3.4 T3.5 T3.6 T4.2 T4.4 T4.5 T4.6 U4.3 U4.5 U9.A1 U9.A2 U9.A3 U9.A4 U9.A5 U9.A6 U9.A8 U9.A9 U9.A10 U9.A11 U9.A12 U9.A13 U9.B1 U9.B2 U9.B3 U9.B4 U9.B5 U9.B6 U9.B7 U9.B8 U9.B9 U9.B10 U9.B11 U9.B12 U9.B13 U9.B14 U9.B15 U9.C2 U9.C3 U9.C4 U9.C11 U9.C12 U9.C13 U9.C14 U9.C15 U9.D1 U9.D2 U9.D3 U9.D4 U9.D10 U9.D11 U9.D13 U9.D14 U9.E1 U9.E2 U9.E3 U9.E4 U9.E12 U9.E13 U9.E14 U9.E15 U9.F1 U9.F4 U9.F14 U9.G4 U9.G14 U9.G15 U9.H1 U9.H2 U9.H3 U9.H4 U9.H14 U9.H15 U9.J2 U9.J3 U9.J4 U9.K1 U9.K2 U9.K3 U9.K12 U9.K14 U9.K15 U9.L1 U9.L3 U9.L12 U9.L13 U9.L14 U9.L15 U9.M2 U9.M3 U9.M4 U9.M5 U9.M6 U9.M7 U9.M12 U9.M13 U9.M14 U9.M15 U9.N2 U9.N4 U9.N5 U9.N6 U9.N7 U9.N11 U9.N13 U9.N14 U9.N15 U9.P2 U9.P4 U9.P5 U9.P6 U9.P7 U9.P8 U9.P9 U9.P10 U9.P11 U9.P12 U9.P13 U9.P14 U9.P15 U9.R2 U9.R3 U9.R6 U9.R7 U9.R8 U9.R9 U9.R10 U9.R11 U9.R12 U9.R13 U11.5 U15.4 U17.1 U17.2

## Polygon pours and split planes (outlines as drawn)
GND on Top Layer "GND_L01_P336" (solid, remove dead copper, pour order 336): 42.65,27.425 41.875,26.65 41.875,23.7 42.4,23.175 45.2,23.175 46.325,22.05 46.85,22.05 46.85,25.95 46.025,26.775 46.025,27.25 45.85,27.425
VOUT on Top Layer "VOUT_L01_P292" (solid, remove dead copper, pour order 292): 37 vertices, not listed, extent 30.8,12.475 51.1,28.2
GND on Top Layer "GND_L01_P262" (solid, remove dead copper, pour order 262): 35.7,104.425 36.875,104.425 37.125,104.175 37.125,102.575 36.9,102.35 33.45,102.35 28.15,102.35 27.65,102.85 27.65,112.125 28.05,112.525 31.225,112.525 31.6,112.15 31.6,105.6 31.95,105.25 34.875,105.25
GND on Top Layer "GND_L01_P120" (solid, remove dead copper, pour order 120): 20.739,99.304 21.264,98.779 21.264,94.454 20.364,93.554 16.539,93.554 15.689,94.404 15.689,98.279 16.714,99.304
5V_USB_STLK on Top Layer "5V_USB_STLK_L01_P090" (solid, remove dead copper, pour order 90): 51.187,107.587 49.85,106.25 49.7,106.275 48.65,106.275 48.625,106.25 48.625,102.725 49.35,102 54.2,102 54.9,102.7 54.9,133.5 54.625,133.775 51.538,133.775 51.188,133.425
GND on Top Layer "GND_L01_P022" (solid, remove dead copper, pour order 22): 39 vertices, not listed, extent 8.95,108.675 23.55,124.075
GND on Top Layer "GND_L01_P018" (solid, remove dead copper, pour order 18): 12.8,109.15 23.65,109.15 23.65,106.675 21.4,104.425 1.4,104.425 0.125,105.7 0.125,120.275 0.4,120.55 6.575,120.55 6.75,120.375 6.75,115.775 5.25,114.275 5.25,110.825 6.925,109.15
GND on Top Layer "GND_L01_P006" (solid, remove dead copper, pour order 6): 132 vertices, not listed, extent 0.075,0.05 55.85,152.275
5V_USBPD on Top Layer "5V_USBPD_L01_P016" (solid, remove dead copper, pour order 16): 10.225,121.275 5.65,121.275 5.125,120.75 1.325,120.75 1.05,121.025 1.05,124.55 1.175,124.675 5.175,124.675 5.525,124.325 5.525,123.775 5.85,123.45 6.85,123.45 8.525,121.775 10.225,121.775
SW2 on Top Layer "SW2_L01_P014" (solid, remove dead copper, pour order 14): 10.25,121.925 8.525,121.925 7.4,123.05 7.4,124.55 7,124.95 1.65,124.95 1.05,125.55 1.05,135.2 1.375,135.525 7.3,135.525 7.6,135.225 7.6,127.225 10.25,124.575
SW1 on Top Layer "SW1_L01_P012" (solid, remove dead copper, pour order 12): 14.6,121.925 16.3,121.925 17.325,122.95 17.325,125.75 15.05,128.025 15.05,134.725 14.225,135.55 8.775,135.55 8.425,135.2 8.425,127.375 10.975,124.825 14.1,124.825 14.575,124.35
V_IN on Top Layer "V_IN_L01_P342" (solid, remove dead copper, pour order 342): 35 vertices, not listed, extent 11.9,10.55 25.1,22.05
NetJP3_1 on Top Layer "NETJP3_1_L01_P340" (solid, remove dead copper, pour order 340): 35.55,11.825 35.55,8.275 35.25,7.975 32.15,7.975 31.8,8.325 31.8,16.8 31.975,16.975 34.325,16.975 34.475,16.825 34.475,12.9
NetJP3_2 on Top Layer "NETJP3_2_L01_P294" (solid, remove dead copper, pour order 294): 22 vertices, not listed, extent 31.8,9.05 38.375,19.85
GND on Top Layer "GND_L01_P274" (solid, remove dead copper, pour order 274): 20 vertices, not listed, extent 33,83.5 44.375,87.375
5V on Top Layer "5V_L01_P258" (solid, remove dead copper, pour order 258): 43.25,106.5 41.925,105.175 40.575,105.175 40.025,104.625 40.025,102.925 40.275,102.675 44.376,102.675 44.776,103.075 47.975,103.075 48.5,103.6 48.5,114.1 48.1,114.5 43.75,114.5 43.25,114
GND on Top Layer "GND_L01_P172" (solid, remove dead copper, pour order 172): 14.55,46.975 14.55,43.075 15.525,42.1 24.25,42.1 24.725,42.575 24.725,47.225 23.175,48.775 23.175,57.175 22.7,57.65 22.1,57.65 12.975,57.625 12.15,56.8 12.15,49.375
GND on Top Layer "GND_L01_P116" (solid, remove dead copper, pour order 116): 23 vertices, not listed, extent 17.464,81.829 32.15,96.1
3V3 on Top Layer "3V3_L01_P094" (solid, remove dead copper, pour order 94): 18 vertices, not listed, extent 33.5,96.25 48.425,101.3
NetC42_2 on Top Layer "NETC42_2_L01_P046" (solid, remove dead copper, pour order 46): 17 vertices, not listed, extent 35.385,105.305 40.425,112.025
NetD10_1 on Top Layer "NETD10_1_L01_P044" (solid, remove dead copper, pour order 44): 41.01,109.055 40.205,108.25 40.205,108.16 41.035,107.33 37.36,107.33 37.21,107.48 37.21,108.855 37.41,109.055
USBPD_VBUS on Top Layer "USBPD_VBUS_L01_P024" (solid, remove dead copper, pour order 24): 25 vertices, not listed, extent 14.6,118.325 21.65,125.6
GND on Top Layer "GND_L01_P332" (solid, remove dead copper, pour order 332): 25.6,8.825 25.5,8.725 25.5,8.05 25.725,7.825 28.05,7.825 28.325,8.1 28.325,8.65 27.925,9.05 27.45,9.05 27.225,8.825
GND on Top Layer "GND_L01_P334" (solid, remove dead copper, pour order 334): 36.375,8.825 36.3,8.75 36.3,8.225 36.625,7.9 36.625,7.4 36.825,7.2 37.65,7.2 38.475,8.025 38.475,8.65 38.3,8.825
NetF1_1 on Top Layer "NETF1_1_L01_P320" (solid, remove dead copper, pour order 320): 18 vertices, not listed, extent 35.3,24.025 46.025,41.65
GND on Top Layer "GND_L01_P272" (solid, remove dead copper, pour order 272): 33.875,95.35 33.75,95.225 33.75,93.05 34.025,92.775 35.625,92.775 36.3,92.1 36.3,88.05 36.825,87.525 38.4,87.525 39.175,88.3 39.175,90.9 34.725,95.35
V_LED on Top Layer "V_LED_L01_P160" (solid, remove dead copper, pour order 160): 17 vertices, not listed, extent 27.8,54.15 36.25,61
NetD6_1 on Top Layer "NETD6_1_L01_P164" (solid, remove dead copper, pour order 164): 27.45,48.45 28.175,49.175 28.175,55.2 27.35,56.025 27.35,60.25 26.875,60.725 23.925,60.725 23.5,60.3 23.5,48.925 23.975,48.45
VIN on Top Layer "VIN_L01_P304" (solid, remove dead copper, pour order 304): 7.725,18.5 7.5,18.275 7.5,14.175 7.325,14 4.975,14 4.75,13.775 4.775,13.75 4.775,11.525 5.05,11.25 6.925,11.25 7.3,10.875 9.425,10.875 10.05,11.5 10.05,18.1 9.65,18.5
NetD8_1 on Top Layer "NETD8_1_L01_P154" (solid, remove dead copper, pour order 154): 35.85,70.9 36,70.75 36,63.7 36.65,63.05 36.65,61.975 36.575,61.9 35.85,61.9 34.575,61.9 33.375,63.1 33.375,71.275 33.85,71.75 35.775,71.75 35.85,71.675
NetD7_1 on Top Layer "NETD7_1_L01_P158" (solid, remove dead copper, pour order 158): 17.85,71.75 18.475,71.75 18.675,71.55 18.675,69.375 18.25,68.95 18.25,62.575 17.65,61.975 15.675,61.975 15.3,62.35 15.3,63.725 15.3,69.025 16.025,69.75 16.175,69.9 16.175,71.55 16.375,71.75
NetJP2_1 on Top Layer "NETJP2_1_L01_P296" (solid, remove dead copper, pour order 296): 19 vertices, not listed, extent 24.675,9.05 31.6,20.675
NetR29_1 on Top Layer "NETR29_1_L01_P306" (solid, remove dead copper, pour order 306): 19 vertices, not listed, extent 7.825,21.625 15.95,40.35
NetR29_2 on Top Layer "NETR29_2_L01_P308" (solid, remove dead copper, pour order 308): 12.575,36.85 12.125,36.4 12.125,22.4 12.275,22.25 16.075,22.25 16.175,22.35 16.175,36.675 16,36.85
NetR30_2 on Top Layer "NETR30_2_L01_P312" (solid, remove dead copper, pour order 312): 16.775,36.825 16.375,36.425 16.375,22.65 16.725,22.3 19.95,22.3 20.7,23.05 20.7,36.55 20.425,36.825
NetR31_2 on Top Layer "NETR31_2_L01_P314" (solid, remove dead copper, pour order 314): 21.175,36.825 20.9,36.55 20.9,23.275 21.175,23 24.825,23 25.1,23.275 25.1,36.55 24.825,36.825
NetR37_1 on Top Layer "NETR37_1_L01_P316" (solid, remove dead copper, pour order 316): 24.175,41.35 24.5,41.675 30.075,41.675 30.75,41 30.75,28.675 30.5,28.425 28.575,28.425 28.25,28.75 28.25,36.7 27.95,37 24.4,37 24.175,37.225
NetF2_1 on Top Layer "NETF2_1_L01_P318" (solid, remove dead copper, pour order 318): 30.6,23.375 30.2,22.975 25.625,22.975 25.3,23.3 25.3,36.5 25.6,36.8 27.825,36.8 28.05,36.575 28.05,28.675 28.5,28.225 30.4,28.225 30.6,28.025
NetR38_2 on Top Layer "NETR38_2_L01_P322" (solid, remove dead copper, pour order 322): 35.7,41.65 35.2,41.15 35.2,28.95 35.375,28.775 39.125,28.775 39.275,28.925 39.275,41.5 39.125,41.65
NetR37_2 on Top Layer "NETR37_2_L01_P324" (solid, remove dead copper, pour order 324): 31.125,41.15 30.95,40.975 30.95,28.675 31.225,28.4 34.7,28.4 35,28.7 35,41.05 34.9,41.15
NetR39_2 on Top Layer "NETR39_2_L01_P326" (solid, remove dead copper, pour order 326): 39.775,41.65 39.475,41.35 39.475,29.075 39.775,28.775 42.7,28.775 43.55,29.625 43.55,41.5 43.4,41.65
NetJP2_2 on Top Layer "NETJP2_2_L01_P338" (solid, remove dead copper, pour order 338): 27.475,12 27.4,11.925 27.4,9.35 27.5,9.25 28.05,9.25 28.525,8.775 28.525,8.175 28.725,7.975 31.25,7.975 31.6,8.325 31.6,16.8 31.425,16.975 29.55,16.975 28.925,16.35 28.925,13.45
VDD on Top Layer "VDD_L01_P128" (solid, remove dead copper, pour order 128): 42.475,96.075 42.075,95.675 42.075,94.31 43.806,92.55 45.8,92.55 47.025,91.325 50.7,91.325 51.2,91.825 51.2,93.525 50.5,94.225 49.1,94.225 47.225,96.1 44.925,96.1 44.9,96.075
V_LED on Top Layer "V_LED_L01_P156" (solid, remove dead copper, pour order 156): 32 vertices, not listed, extent 20.024,66.325 40.9,72.975
GND on Top Layer "GND_L01_P174" (solid, remove dead copper, pour order 174): 18 vertices, not listed, extent 26.85,43.625 43.8,57.3
GND on Signal Layer 2 "GND_L03_P280" (solid, remove dead copper, pour order 280): 21 vertices, not listed, extent 21.225,118.927 33.849,152.275
3V3_STLK on Signal Layer 2 "3V3_STLK_L03_P266" (solid, remove dead copper, pour order 266): 17 vertices, not listed, extent 33.5,111.375 43.75,127.035
GND on Signal Layer 2 "GND_L03_P264" (solid, remove dead copper, pour order 264): 47.075,125.65 48.425,124.3 48.425,118.625 47.425,117.625 44.7,117.625 42.725,119.6 42.725,124.9 43.475,125.65
5V_USB_CHGR on Signal Layer 2 "5V_USB_CHGR_L03_P260" (solid, remove dead copper, pour order 260): 25 vertices, not listed, extent 40.145,110.975 55,151.15
3V3_STLK on Signal Layer 2 "3V3_STLK_L03_P030" (solid, remove dead copper, pour order 30): 23 vertices, not listed, extent 28.525,125.85 49.625,151.5
GND on Signal Layer 2 "GND_L03_P068" (solid, remove dead copper, pour order 68): 20 vertices, not listed, extent 11.61,111.1 36.4,120.875
GND on Signal Layer 2 "GND_L03_P008" (solid, remove dead copper, pour order 8): 21 vertices, not listed, extent 0,117.5 23.805,152.325
USBPD_VBUS on Signal Layer 2 "USBPD_VBUS_L03_P066" (solid, remove dead copper, pour order 66): 21 vertices, not listed, extent 5.05,115.73 22.46,138.45
AGND on Signal Layer 2 "AGND_L03_P328" (solid, remove dead copper, pour order 328): 12.65,9.675 11.95,8.975 11.95,3.75 12.425,3.275 15.475,3.275 16.975,4.775 16.975,6.3 16.975,8 16.525,8.45 16.525,9.35 16.2,9.675
5V_USBPD on Signal Layer 2 "5V_USBPD_L03_P060" (solid, remove dead copper, pour order 60): 37 vertices, not listed, extent 1.05,107.35 51.175,124.9
GND on Signal Layer 2 "GND_L03_P070" (solid, remove dead copper, pour order 70): 7.85,108.375 8.225,108 8.225,106.75 4.05,102.575 4.05,91.625 5.203,90.472 5.203,89.825 0.375,89.825 0.112,90.088 0.112,107.712 0.1,107.725 0.1,113.55 0.175,113.625 2.6,113.625 5.95,110.275
5V_VIN on Signal Layer 2 "5V_VIN_L03_P064" (solid, remove dead copper, pour order 64): 23 vertices, not listed, extent 4.325,95.8 51.1,108.675
5V_OUT on Signal Layer 2 "5V_OUT_L03_P082" (solid, remove dead copper, pour order 82): 21 vertices, not listed, extent 4.4,90.925 37.525,104.375
3V3 on Signal Layer 2 "3V3_L03_P096" (solid, remove dead copper, pour order 96): 33.825,101.25 33.525,100.95 33.525,100.65 33.875,100.3 35.4,100.3 38.8,96.9 49.8,96.9 50.325,97.425 50.325,100.525 49.6,101.25
GND on Signal Layer 2 "GND_L03_P114" (solid, remove dead copper, pour order 114): 79 vertices, not listed, extent 0.075,0.073 55.88,113.65
AGND on Signal Layer 2 "AGND_L03_P118" (solid, remove dead copper, pour order 118): 22 vertices, not listed, extent 31.75,85.4 51.15,95.9
VDD on Signal Layer 2 "VDD_L03_P122" (solid, remove dead copper, pour order 122): 52 vertices, not listed, extent 14.325,77.675 51.3,100.1
AVDD on Signal Layer 2 "AVDD_L03_P134" (solid, remove dead copper, pour order 134): 30.55,91.675 31.125,91.1 31.125,84.75 31.675,84.2 43.725,84.2 50.5,84.2 51.375,83.325 51.375,80.975 50.8,80.4 30.3,80.4 29.625,81.075 29.625,91.5 29.8,91.675
V_LED on Signal Layer 2 "V_LED_L03_P150" (solid, remove dead copper, pour order 150): 27.875,55.45 35.4,55.45 43.525,63.575 43.525,72.225 43.15,72.6 21.575,72.6 19.525,70.55 19.525,63.8
GND on Signal Layer 2 "GND_L03_P180" (solid, remove dead copper, pour order 180): 34.058,53.458 44.575,63.975 51.4,63.975 55.825,59.55 55.825,44.75 55.65,44.575 34.036,44.575
VREF on Signal Layer 2 "VREF_L03_P256" (solid, remove dead copper, pour order 256): 46.825,88.375 46.45,88 40.25,88 40.025,87.775 40.025,85.925 40.425,85.525 51.175,85.525 51.475,85.825 51.475,88.025 51.125,88.375
GND on Signal Layer 2 "GND_L03_P276" (solid, remove dead copper, pour order 276): 34 vertices, not listed, extent 29,84.3 39.875,96.875
GND on Signal Layer 2 "GND_L03_P278" (solid, remove dead copper, pour order 278): 38.15,91.95 37.6,91.4 37.6,90.975 37.75,90.825 38,90.825 38.55,91.375 45.75,91.375 45.925,91.55 45.925,91.8 45.775,91.95
GND on Signal Layer 2 "GND_L03_P330" (solid, remove dead copper, pour order 330): 12.75,2.95 12.75,0.1 12.775,0.075 14.375,0.075 14.375,2.95
V_LED on Bottom Layer "V_LED_L04_P152" (solid, remove dead copper, pour order 152): 19 vertices, not listed, extent 25.025,54.25 36.2,70.025
5V on Bottom Layer "5V_L04_P136" (solid, remove dead copper, pour order 136): 34 vertices, not listed, extent 33.775,61.7 48.4,116.9
3V3 on Bottom Layer "3V3_L04_P098" (solid, remove dead copper, pour order 98): 31.925,114.9 31.925,112.915 32.575,112.232 32.575,105.375 34.6,103.35 34.6,100.45 34.4,100.25 33.65,100.25 30.65,103.25 30.65,105.375 30.65,115.525 30.784,115.659 31.166,115.659
USBPD_VBUS on Bottom Layer "USBPD_VBUS_L04_P054" (solid, remove dead copper, pour order 54): 23 vertices, not listed, extent 5.75,99.95 22.875,125.55
GND on Bottom Layer "GND_L04_P010" (solid, remove dead copper, pour order 10): 48 vertices, not listed, extent 0.075,103.2 55.88,152.3
NetC102_2 on Bottom Layer "NETC102_2_L04_P286" (solid, remove dead copper, pour order 286): 8.175,104.3 7.975,104.1 1.325,104.1 1.125,104.3 1.125,106.45 1.45,106.775 7.175,106.775 8.175,105.775
3V3 on Bottom Layer "3V3_L04_P138" (solid, remove dead copper, pour order 138): 35.45,100.321 35.779,100.65 37.192,100.65 37.525,100.321 37.525,99.7 36.025,98.2 36.025,91.6 35.825,91.4 34.775,91.4 34.525,91.65 34.525,99.1 35.45,100.025
GND on Bottom Layer "GND_L04_P284" (solid, remove dead copper, pour order 284): 69 vertices, not listed, extent 0.325,0.2 55.762,135.612
USB_PD_VBUS on Bottom Layer "USB_PD_VBUS_L04_P290" (solid, remove dead copper, pour order 290): 1.125,97.45 1.125,14.55 2.1,13.575 7.8,13.575 8.375,14.15 8.375,17.425 7.8,18 4.625,18 3.35,19.275 3.35,98.3 5.525,100.475 5.525,103.575 5.2,103.9 1.3,103.9 1.125,103.725
GND on Signal Layer 1 "GND_L02_P004" (solid, remove dead copper, pour order 4): 10.525,152.4 10.5,152.425 0.85,152.425 -0.025,151.55 -0.025,1 0.95,0.025 54.825,0.025 55.88,1.08 55.88,151.295 54.775,152.4

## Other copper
Top Layer:
  pour cut-out: 41.025,143.275 41.45,143.7 42.25,143.7 42.475,143.475 42.475,142.45 41.519,141.494 40.469,141.494 40.349,141.614 40.349,143.044 40.58,143.275
  pour cut-out: 29.196,140.419 29.196,131.959 30.164,130.991 34.589,130.991 34.63,131.032 34.63,132.525 31.48,132.525 30.505,133.5 30.53,133.525 30.53,143.575 31.73,144.775 38.805,144.775 39.096,145.066 39.096,145.959 37.356,145.959 37.34,145.975 32.255,145.975 31.33,145.05 28.426,145.05 27.705,144.329 27.705,141.325 28.605,140.425 28.705,140.425
  pour cut-out: 33.43,141.725 33.43,135.225 39.93,135.225 39.93,141.725
  pour cut-out: 14.15,49.9 13.3,49.05 13.3,48.2 14.275,47.225 15.2,47.225 15.575,47.6 15.575,49.45 15.125,49.9
  pour cut-out: 15.45,42.7 21.675,42.7 22.15,42.225 22.15,41.55 15.775,41.55 15.45,41.875
  text "1" at 2.145,140.09 h2.5
Signal Layer 1:
  text "2" at 3.895,140.09 h2.5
